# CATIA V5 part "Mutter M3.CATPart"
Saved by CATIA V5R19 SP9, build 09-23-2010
Part number: Mutter M3
Bounding box of the stored display mesh (mm): x -2.75 to 2.75, y -3.175 to 3.175, z 0 to 2.4
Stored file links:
  D:\Temporäre Sachen\Lasermodul KY-008 with mounting for adjustment\Mutter M3.CATPart
  d:\Program Files\Dassault Systemes\B19\win_b64\reffiles\standard\MetricThickPitch.txt
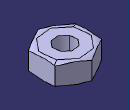
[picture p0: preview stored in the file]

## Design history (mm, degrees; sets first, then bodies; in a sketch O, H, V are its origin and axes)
AxisSystem1: origin (0, 0, 0), X (1, 0, 0), Y (0, 1, 0), Z (0, 0, 1)
Body1 (main body)
  Sketch1 on xy-plane, origin (0, 0, 0), H (1, 0, 0), V (0, 1, 0)
    point P1 (2.75, -1.5877)
    point P2 (2.75, 1.5877)
    point P3 (0, 3.1754)
    point P4 (-2.75, 1.5877)
    point P5 (-2.75, -1.5877)
    point P6 (0, -3.1754)
    point P7 (2.75, 0)
    line L1 (2.75, -1.5877) -> (2.75, 1.5877)
    line L2 (2.75, 1.5877) -> (0, 3.1754)
    line L3 (0, 3.1754) -> (-2.75, 1.5877)
    line L4 (-2.75, 1.5877) -> (-2.75, -1.5877)
    line L5 (-2.75, -1.5877) -> (0, -3.1754)
    line L6 (0, -3.1754) -> (2.75, -1.5877)
    construction line L7 (0, 0) -> (2.75, 0)
    construction circle A1 centre (0, 0) radius 3.1754
    construction arc A2 centre (-2.75, -1.5877) radius 3.1754 from (-2.75, 1.5877) to (0, -3.1754) cw
    construction arc A3 centre (2.75, 1.5877) radius 3.1754 from (0, 3.1754) to (2.75, -1.5877) ccw
    distance L1 L4 = 5.5
    horizontal: L7 H
    coincidence: A1 P1, A1 P2, A1 P3, A1 P4, A1 P5, A1 P6, A2 O, A3 O
    midpoint: P7 L1
    parallelism: L1 L4
  Pad1: profile Sketch1, direction (0, 0, 1), length 2.4
  Sketch2 on xy-plane, origin (0, 0, 0), H (1, 0, 0), V (0, 1, 0)
    point P1 (0, 0)
    coincidence: P1 O
  Sketch3 on start face of Pad1, origin (0, 0, 0), H (1, 0, 0), V (0, -1, 0)
    point P1 (0, 0)
    reference projected point E1 (0, 0) from Sketch2.P1
    coincidence: E1 P1
  Hole1: placed by Sketch3, at (0, 0, 0) direction (0, 0, 1), diameter 2.459, depth 10, threaded "M3", thread diameter 3, thread depth 10, pitch 0.5
  Sketch4 on zx-plane, origin (0, 0, 0), H (-1, 0, 0), V (0, 0, 1)
    construction line L1 (0, -0.872) -> (0, 3.2614)
    point P1 (0, -0.872)
    line L2 (0, 0) -> (2.5, 0)
    point P3 (2.5, 0)
    arc A1 centre (2.5, 1.5) radius 1.5 from (2.5, 0) to (3.3, 0.2311) ccw
    point P4 (2.5, 1.5)
    point P5 (3.3, 0.2311)
    line L3 (3.3, 0.2311) -> (3.3, -0.644)
    point P6 (3.3, -0.644)
    line L4 (3.3, -0.644) -> (0, -0.644)
    point P7 (0, -0.644)
    axis line L5 (6.8151, 1.2) -> (-5.6256, 1.2)
    point P10 (0, 3.044)
    point P11 (3.3, 3.044)
    point P12 (3.3, 2.1689)
    point P13 (2.5, 2.4)
    point P14 (0, 2.4)
    line L6 (3.3, 3.044) -> (0, 3.044)
    line L7 (3.3, 2.1689) -> (3.3, 3.044)
    arc A2 centre (2.5, 0.9) radius 1.5 from (2.5, 2.4) to (3.3, 2.1689) cw
    line L8 (0, 2.4) -> (2.5, 2.4)
    line L9 (0, 3.044) -> (0, 2.4)
    line L10 (0, -0.644) -> (0, 0)
    radius A1 = 1.5
    distance L3 P4 = 0.8
    distance L1 P4 = 2.5
    distance L2 L4 = 0.644
    distance H L5 = 1.2
    coincidence: P1 V, P7 L1
    vertical: L1 V, L3 V, L9 V, L10 V
    horizontal: L2 H, L4 H, L5 H
    tangency: A1 L2
    symmetry: P7 P10 L5, P6 P11 L5, P5 P12 L5, P3 P13 L5, O P14 L5, L4 L6 L5, L3 L7 L5, A1 A2 L5, L2 L8 L5
  Groove1: profile Sketch4.L2, Sketch4.L8, axis Sketch4.V, angle 360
